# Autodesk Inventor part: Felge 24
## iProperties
Shininess: 64.0
Length Units: 11269
Angle Units: 11279
Time Units: 11290
Mass Units: 11283
Length Display Precision: 3
Angle Display Precision: 2
Compacted: True
Part Number: Felge 24
Document SubType Name: Modeling
Created: 2003-10
Material: Delrin, White
Designer: Bernhard Fetzer
Manufacturer: Standard
Standards Organization: Custom
Density: 0.0
Volumn: 0.0
Area: 0.0
PropertySet Name: Model Information
Control State: 0
Master: False
Checked Out: False
Author: Bernhard Fetzer
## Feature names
1. Extrusion1
2. Revolution1
3. Extrusion2
4. Extrusion3
5. Chamfer1
6. Extrusion4
7. Extrusion5
8. Circular Pattern1
9. Extrusion6
10. Extrusion7
